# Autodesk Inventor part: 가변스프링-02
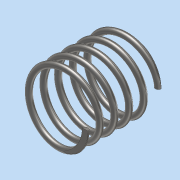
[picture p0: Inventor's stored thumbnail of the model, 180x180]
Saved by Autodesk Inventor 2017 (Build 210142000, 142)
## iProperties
Part Number: 가변스프링-02
Material: 강철, 연강
Document SubType Name: Modeling
Designer: MRC
Density: 7.85 g/cm^3
Appearance: 반연마
Mass: 8.38159 g
Surface Area: 21.6554 cm^2
Volume: 1.06772 cm^3
Author: MRC
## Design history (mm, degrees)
sketch "스케치1"
  geometry: L1 (0, 0)-(11, 0); L2 (11, 0)-(11, 25.358); L3 (11, 25.358)-(0, 25.358); L4 (0, 25.358)-(0, 0); C1 r 1 at (11, 0)
  constraints: 8 end point, 2 parallel, 1 centre point, 1 coincident, 1 horizontal, 1 perpendicular
  dimensions: "d0" = 25.35829 distance of L3.end L1.start (derived); "d1" = 22 diameter of L2 L4; "d2" = 2 diameter of C1
feature "코일1" sketch "스케치1" pitch "d3" = 10; turns "d5" = 5; dims "d4" = 25.35829 (= d0), "d6" = 0, angle "d7" = 90 deg, angle "d8" = 90 deg, "d9" = 0, "d10" = 0
sketch "스케치2"
  geometry: L1 (25.358, 17.383)-(0, 17.383); L2 (0, 17.383)-(0, -17.383); L3 (0, -17.383)-(25.358, -17.383); L4 (25.358, -17.383)-(25.358, 17.383); 2 further points
  constraints: 8 end point, 2 parallel, 1 coincident, 1 horizontal, 1 midpoint, 1 perpendicular
  dimensions: "d11" = 25.35829 distance of L2.end L3.end (= d0); "d12" = 34.76604 distance of L3.end L1.start
extrude "돌출1" sketch "스케치2" stored distance "d13" = 47.75; taper "d14" = 0 deg
node "솔리드1"
